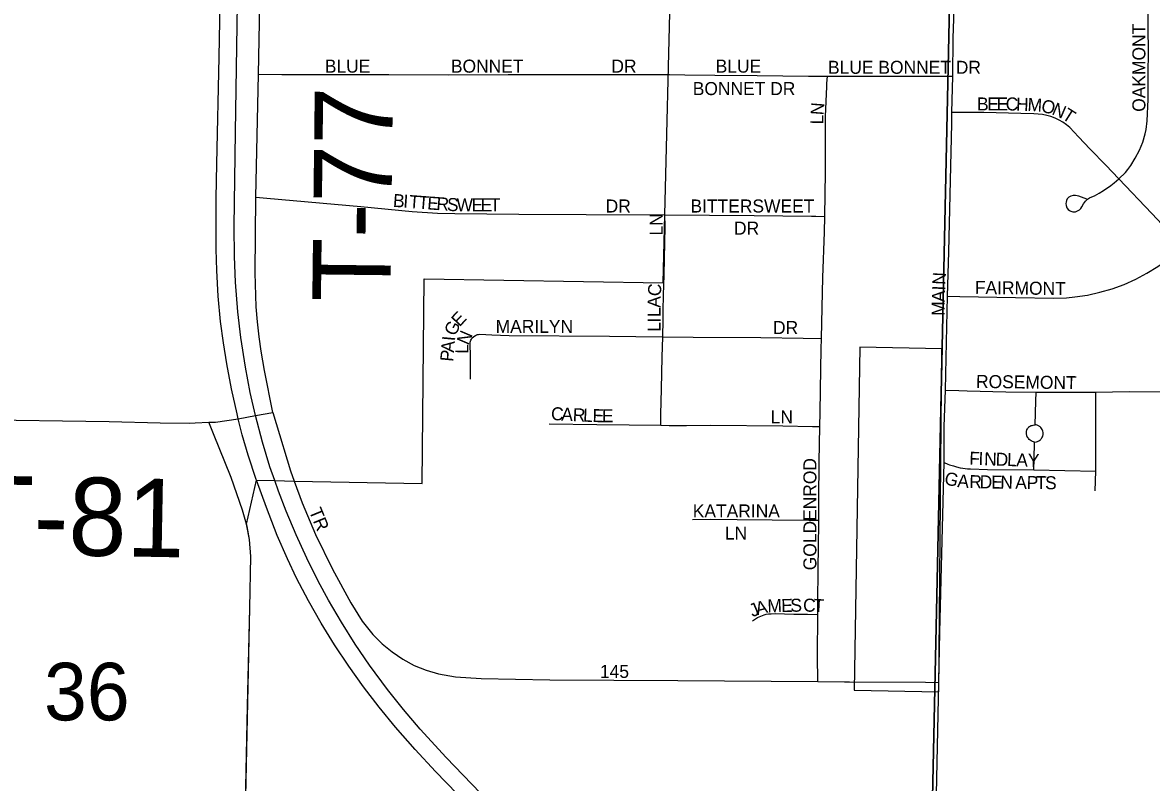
# Model space of a CAD drawing. Extents: x 1587405 to 1714697, y 1028970 to 1155083.
# Drawn here: x 1647315 to 1651648, y 1094719 to 1097636 of the extents above; entities that cross this region are included whole.
import ezdxf

# ---------------------------------------------------------------- set-up
doc = ezdxf.new("R2010")
doc.units = 0
for name, color, linetype in [('GM_X_City_Street', 7, 'Continuous'), ('GM_X_City_Street_Text', 7, 'Continuous'), ('GM_X_Corporation', 7, 'Continuous'), ('GM_X_Section', 7, 'Continuous'), ('GM_X_Section_Text', 7, 'Continuous'), ('GM_X_Township_Road', 7, 'Continuous'), ('GM_X_Township_Road_Text', 7, 'Continuous'), ('GM_X_Township_Subdivision', 7, 'Continuous'), ('GM_X_Township_Subdivision_Text', 7, 'Continuous'), ('GM_X_US_Route', 7, 'Continuous')]:
    doc.layers.add(name, color=color, linetype=linetype)

msp = doc.modelspace()

# ---------------------------------------------------------------- linework, layer by layer
at = {"layer": 'GM_X_City_Street'}
for points in [[(1650885.8, 1097429.9), (1650887.7, 1097576.5), (1650890.6, 1097688)], [(1651523.4, 1097036), (1651548.5, 1097060.6), (1651558.2, 1097072.2), (1651569.1, 1097087.2), (1651586.4, 1097116.2), (1651601.9, 1097145.8), (1651614.6, 1097176.7), (1651624.4, 1097208.8), (1651627.9, 1097225.3), (1651632, 1097258.6), (1651635.6, 1097341.1), (1651635.8, 1097374.3), (1651635.2, 1097407.5), (1651636.4, 1097556.2), (1651635.8, 1097585.7), (1651635.5, 1097635.4), (1651635.3, 1097685.8)], [(1649797.9, 1097436.5), (1649856.5, 1097435.3), (1649971.9, 1097434.7), (1650134.8, 1097433.1), (1650332.4, 1097430.7), (1650405.1, 1097430.5)], [(1650394, 1096891.5), (1650397, 1097061.4), (1650396.8, 1097275.7), (1650401.9, 1097391.1), (1650402.8, 1097402.6), (1650405.1, 1097430.5)], [(1650405.1, 1097430.5), (1650497.2, 1097430.2), (1650858.6, 1097429.9), (1650885.8, 1097429.9)], [(1650882.5, 1097290.6), (1650885.8, 1097429.9)], [(1650865.5, 1096586), (1650869.9, 1096756.5), (1650881.5, 1097248.5), (1650882.5, 1097290.6)], [(1651523.4, 1097036), (1651472.8, 1097088.4), (1651413, 1097150.2), (1651368.3, 1097198.2), (1651335.1, 1097233), (1651322.3, 1097244), (1651308.4, 1097253.7), (1651293.8, 1097262.2), (1651278.5, 1097269.3), (1651262.7, 1097275.2), (1651246.5, 1097279.8), (1651230, 1097283.1), (1651196.7, 1097286.3), (1651147.2, 1097287.6), (1651004.3, 1097290.7), (1650918.8, 1097290.6), (1650882.5, 1097290.6)], [(1651400.5, 1096958.2), (1651369.2, 1096969.7), (1651362.9, 1096971.3), (1651356.2, 1096972.8), (1651347.5, 1096972.3), (1651339, 1096970), (1651331.6, 1096965.9), (1651325.3, 1096959.1), (1651322.5, 1096953.8), (1651320.5, 1096947.1), (1651320.1, 1096941.4), (1651320.9, 1096933.4), (1651324, 1096925.3), (1651329.2, 1096918.4), (1651334.2, 1096914.5), (1651339.2, 1096911.7), (1651346.8, 1096909.5), (1651352.1, 1096909.5), (1651357, 1096910.2), (1651364.8, 1096913.3), (1651371.9, 1096917.3), (1651376.7, 1096922.1), (1651381.4, 1096929.5), (1651387.3, 1096939.9), (1651391.4, 1096945.6), (1651395.5, 1096950.4), (1651402.7, 1096957.8), (1651406.6, 1096961.1), (1651410.1, 1096963.3), (1651420, 1096967.5), (1651429.2, 1096971.7), (1651448.1, 1096981.9), (1651464.5, 1096991.5), (1651492.1, 1097010.5), (1651505, 1097021.3), (1651523.4, 1097036)], [(1651769, 1096776.9), (1651649.2, 1096903.2), (1651523.4, 1097036)], [(1649776.6, 1096628.6), (1649777.8, 1096668.4), (1649781.5, 1096853.5), (1649780.3, 1096898.1)], [(1649780.3, 1096898.1), (1650123.4, 1096895.7), (1650343.3, 1096893.5), (1650359.7, 1096892.9), (1650394, 1096891.5)], [(1650381.9, 1096423.3), (1650384.8, 1096542.5), (1650387.1, 1096657.5), (1650393, 1096832), (1650394, 1096891.5)], [(1650865.5, 1096586), (1650913.2, 1096585), (1651126.1, 1096580.3), (1651273.5, 1096578.9), (1651322.4, 1096580.2), (1651354.7, 1096582.8), (1651402.8, 1096590.4), (1651450.5, 1096601.3), (1651497.5, 1096614.6), (1651543.4, 1096631), (1651587.9, 1096651), (1651630.9, 1096674.1), (1651672.4, 1096699.9), (1651712.2, 1096728.3), (1651750, 1096759.1), (1651769, 1096776.9)], [(1649772.7, 1096430.2), (1649772.8, 1096446.3), (1649773.3, 1096478.9), (1649774.3, 1096531.3), (1649775.1, 1096590.2), (1649776.6, 1096628.6)], [(1650861.4, 1096409.8), (1650864, 1096526.9), (1650865.5, 1096586)], [(1649034.5, 1096266.9), (1649034, 1096295.4), (1649033.8, 1096348.7), (1649033.7, 1096409), (1649034.4, 1096413.5), (1649035.6, 1096416.7), (1649037.6, 1096420.6), (1649041.3, 1096425.5), (1649045.5, 1096429.7)], [(1649045.5, 1096429.7), (1649050.4, 1096433.4), (1649054, 1096435.5), (1649057, 1096437), (1649060.7, 1096438.3), (1649064.9, 1096439.2), (1649070.8, 1096439.7), (1649116.4, 1096437.4), (1649183.4, 1096435.6), (1649567.5, 1096432.6), (1649669.3, 1096431.4), (1649772.7, 1096430.2)], [(1649765.1, 1096090.7), (1649765.5, 1096131.6), (1649767.6, 1096230.6), (1649770.4, 1096351.4), (1649772.7, 1096430.2)], [(1649772.7, 1096430.2), (1649888.5, 1096428.8), (1650148.9, 1096427.2), (1650311.6, 1096424.8), (1650381.9, 1096423.3)], [(1650375.5, 1096085.3), (1650376.4, 1096140.2), (1650379, 1096307.6), (1650380.8, 1096382.5), (1650381.9, 1096423.3)], [(1650857.3, 1096224.8), (1650861.4, 1096409.8)], [(1650853.2, 1096086.2), (1650857.3, 1096224.8)], [(1650857.3, 1096224.8), (1650908.8, 1096223.4), (1650941.5, 1096222.5), (1651088.8, 1096218.4), (1651206.1, 1096218.1)], [(1651202.3, 1096092.3), (1651205, 1096183.3), (1651206.1, 1096218.1)], [(1651206.1, 1096218.1), (1651285.1, 1096217.8), (1651435, 1096217.8)], [(1651434.3, 1095914.1), (1651435.4, 1096152.3), (1651435, 1096217.8)], [(1651435, 1096217.8), (1651563, 1096220.1), (1651969, 1096215.9)], [(1649336.1, 1096096.5), (1649518.9, 1096093.9), (1649643.5, 1096092.1), (1649765.1, 1096090.7)], [(1649765.1, 1096090.7), (1649797.6, 1096090.1), (1649863.2, 1096089.5), (1649955, 1096090.2), (1650233.8, 1096088.2), (1650347.4, 1096085.8), (1650375.5, 1096085.3)], [(1650371.6, 1095726), (1650372, 1095805.5), (1650373.3, 1095949.9), (1650375.5, 1096085.3)], [(1650852.6, 1095947.4), (1650853.2, 1096086.2)], [(1651199.4, 1096026), (1651192.3, 1096028.1), (1651186, 1096031), (1651182.4, 1096033.5), (1651179.3, 1096036.2), (1651176.6, 1096039.4), (1651174.7, 1096041.7), (1651173, 1096044.1), (1651171.4, 1096046.8), (1651170.5, 1096049.1), (1651169.5, 1096051.9), (1651168.8, 1096055), (1651168.3, 1096058.1), (1651168.1, 1096061.5), (1651168.3, 1096064.3), (1651168.7, 1096067.1), (1651170.5, 1096073), (1651172, 1096076.5), (1651174.2, 1096079.7), (1651176.1, 1096082), (1651178.2, 1096084.1), (1651180.6, 1096085.9), (1651183.9, 1096087.7), (1651186.7, 1096089), (1651190.2, 1096090.1), (1651194.8, 1096091), (1651202.3, 1096092.3)], [(1651199.4, 1096026), (1651206.5, 1096026.9), (1651210.6, 1096028.1), (1651213.7, 1096029.4), (1651216.3, 1096030.7), (1651219.5, 1096032.7), (1651221.9, 1096034.8), (1651223.7, 1096036.9), (1651225.7, 1096039.3), (1651227.9, 1096042.4), (1651229.5, 1096045.5), (1651230.8, 1096048.4), (1651231.7, 1096051.4), (1651232.1, 1096054.1), (1651232.5, 1096059.2), (1651232.1, 1096063.1), (1651231.2, 1096067.2), (1651229.7, 1096071), (1651228.3, 1096074.3), (1651225.8, 1096078.1), (1651223.3, 1096081.4), (1651221, 1096083.8), (1651218.9, 1096085.7), (1651216.8, 1096087.2), (1651214.5, 1096088.5), (1651212.1, 1096089.7), (1651209.4, 1096090.6), (1651206, 1096091.6), (1651202.3, 1096092.3)], [(1651196.7, 1095918.9), (1651197.9, 1095960.5), (1651199.4, 1096026)], [(1650832, 1095103.5), (1650836.3, 1095296.8), (1650852.6, 1095947.4)], [(1650852.6, 1095947.4), (1650866.8, 1095941.5), (1650873.6, 1095938.7), (1650888.3, 1095934.2), (1650900, 1095930.7), (1650914.3, 1095927.4), (1650924.9, 1095925.5), (1650942.7, 1095923.8), (1650953.9, 1095923.2), (1651019.5, 1095920.7), (1651196.7, 1095918.9)], [(1651196.7, 1095918.9), (1651434.3, 1095914.1)], [(1651432.5, 1095838.9), (1651434.3, 1095914.1)], [(1648357.4, 1095876.4), (1648387.9, 1095792.1), (1648439.6, 1095671.2), (1648504.2, 1095538.2), (1648574.9, 1095408.4), (1648619, 1095338.7), (1648659.9, 1095286.8), (1648695, 1095251.6), (1648733.3, 1095220.1), (1648774.6, 1095192.3), (1648818.3, 1095168.7), (1648864.3, 1095149.9), (1648912.1, 1095136.3), (1648977.3, 1095125.4), (1649075.8, 1095118.5), (1649338.4, 1095113.4), (1649830.4, 1095111.3), (1650367.1, 1095106.6)], [(1649886.7, 1095729.3), (1649955.9, 1095729.4), (1650057.6, 1095729.1), (1650192.1, 1095727.9), (1650333.2, 1095726.4), (1650371.6, 1095726)], [(1650367.2, 1095364.1), (1650367.5, 1095401.9), (1650369.5, 1095546.3), (1650370.6, 1095618.5), (1650371.6, 1095723.5), (1650371.6, 1095726)], [(1650117.2, 1095340.3), (1650136.3, 1095352.2), (1650149, 1095358.1), (1650161.3, 1095362.5), (1650169.6, 1095364.7), (1650178.8, 1095366.4), (1650188.6, 1095367.2), (1650203.5, 1095367.7), (1650276.1, 1095365.7), (1650328.6, 1095364.8), (1650367.2, 1095364.1)], [(1650367.1, 1095106.6), (1650365.9, 1095205), (1650367.2, 1095364.1)], [(1650367.1, 1095106.6), (1650469.9, 1095106), (1650489.8, 1095105.8)], [(1650799.6, 1093622.9), (1650804.2, 1093857.2), (1650806.7, 1093968.4), (1650814.6, 1094247.2), (1650814.1, 1094296.5), (1650823, 1094673.5), (1650828, 1094919.6), (1650832, 1095103.5)]]:
    msp.add_lwpolyline(points, dxfattribs=at)
at = {"layer": 'GM_X_Corporation'}
msp.add_lwpolyline([(1648138.8, 1093097.3), (1648187.1, 1095389), (1648190.6, 1095586.4), (1648186.1, 1095652.4), (1648174.5, 1095711.3), (1648212.8, 1095880), (1648282.8, 1095878.2), (1648357.4, 1095876.4), (1648848.2, 1095866.6), (1648856.9, 1096652.9), (1649773.5, 1096636.9), (1649780.3, 1096898.1), (1649801.5, 1097777.7)], dxfattribs=at)
msp.add_lwpolyline([(1650529.5, 1096390.2), (1650506.5, 1095073.1), (1650832.5, 1095067.4), (1650843.4, 1096383.5)], close=True, dxfattribs=at)
at = {"layer": 'GM_X_Section'}
for points in [[(1645545.8, 1097805.3), (1650873.6, 1097703.2), (1650760.9, 1092453), (1645465, 1092544.3)], [(1650873.6, 1097703.2), (1656123.9, 1097642.2), (1656039.3, 1092397.9), (1655871.3, 1092400.1), (1650760.9, 1092453)]]:
    msp.add_lwpolyline(points, close=True, dxfattribs=at)
at = {"layer": 'GM_X_Township_Road'}
for points in [[(1648220, 1097437.7), (1648226.8, 1097771.2)], [(1648210.5, 1096966.1), (1648220, 1097437.7)], [(1648275.4, 1096139.9), (1648243.9, 1096300.1), (1648231.1, 1096375.2), (1648223.3, 1096430), (1648216.9, 1096487.1), (1648212, 1096544.6), (1648207.3, 1096676.1), (1648210.5, 1096966.1)], [(1647110.1, 1096112.9), (1647647.8, 1096105.2), (1647843.1, 1096099.7), (1647957.3, 1096098.3), (1647977.5, 1096099.3)], [(1648030.3, 1096101.8), (1648055.3, 1096102.9), (1648143.1, 1096115.6)], [(1648143.1, 1096115.6), (1648208.8, 1096128.3)], [(1648208.8, 1096128.3), (1648275.4, 1096139.9)], [(1648275.4, 1096139.9), (1648287.9, 1096097.4), (1648343.1, 1095915.7), (1648357.4, 1095876.4)], [(1647977.5, 1096099.3), (1648030.3, 1096101.8)], [(1648138.8, 1093097.3), (1648143.9, 1093353.9), (1648162.5, 1094207.7), (1648166.9, 1094454.1), (1648178.3, 1095012.2), (1648187.1, 1095389), (1648190.6, 1095586.4), (1648186.1, 1095652.4), (1648177.2, 1095701.4), (1648174.5, 1095711.3), (1648159.6, 1095765), (1648116.2, 1095889.3), (1648048.4, 1096057), (1648030.3, 1096101.8)], [(1650489.8, 1095105.8), (1650781.3, 1095103.8), (1650832, 1095103.5)]]:
    msp.add_lwpolyline(points, dxfattribs=at)
at = {"layer": 'GM_X_Township_Subdivision'}
for points in [[(1648220, 1097437.7), (1648310.2, 1097436.7), (1648432.6, 1097437), (1648720.8, 1097437.2), (1648949.6, 1097435.8), (1649178.5, 1097436.9), (1649603.4, 1097436.4), (1649797.9, 1097436.5)], [(1648210.5, 1096966.1), (1648253, 1096962.3), (1648613.3, 1096929.8), (1648809.8, 1096911.2), (1648908.1, 1096905.1), (1648973.7, 1096903.6), (1649220.5, 1096900.2), (1649478.1, 1096899.2), (1649780.3, 1096898.1)]]:
    msp.add_lwpolyline(points, dxfattribs=at)
at = {"layer": 'GM_X_US_Route'}
for points in [[(1648282.8, 1095878.2), (1648264.6, 1095930.6), (1648235.8, 1096025), (1648208.8, 1096128.3), (1648189, 1096216.7), (1648170.8, 1096313.7), (1648153.1, 1096427.5), (1648141.5, 1096525.4), (1648132.3, 1096640.2), (1648127.9, 1096738.8), (1648126.5, 1096853.9), (1648131.8, 1097215.2), (1648140.3, 1097707.7), (1648150.3, 1098233), (1648157.9, 1098676.3), (1648165.1, 1099070.3), (1648170.9, 1099365.8), (1648182.1, 1099891.1), (1648186.6, 1100203), (1648190.4, 1100400.1), (1648190.9, 1100425.2)], [(1649318.9, 1094329.7), (1648899.5, 1094761.5), (1648821.3, 1094845.4), (1648745.9, 1094931.8), (1648683.7, 1095007.8), (1648623.9, 1095085.8), (1648566.9, 1095165.9), (1648512.6, 1095247.7), (1648461, 1095331.3), (1648412.3, 1095416.7), (1648366.7, 1095503.6), (1648331.4, 1095577.5), (1648292.5, 1095667.7), (1648250.8, 1095774.5), (1648212.7, 1095880), (1648211.9, 1095882.4), (1648181.2, 1095975.8), (1648158.4, 1096054.3), (1648143.1, 1096115.6), (1648138.5, 1096133.7), (1648117.4, 1096229.7), (1648098.7, 1096326.3), (1648085.6, 1096407), (1648075.3, 1096488.2), (1648066.3, 1096586.1), (1648060.3, 1096684.1), (1648058, 1096766), (1648058.2, 1096962.7), (1648060.6, 1097093.8), (1648070.1, 1097503.8), (1648074.4, 1097782.7)], [(1649252.7, 1094492.5), (1649203.2, 1094543.2), (1648941.5, 1094815.6), (1648841.2, 1094924.3), (1648776.6, 1094998.8), (1648715.2, 1095076.2), (1648647.1, 1095169), (1648591.6, 1095250.6), (1648538.7, 1095334), (1648488.9, 1095419.2), (1648449.7, 1095491.4), (1648405.8, 1095579.9), (1648365, 1095669.7), (1648326.6, 1095760.6), (1648296.9, 1095837.3), (1648282.8, 1095878.2)]]:
    msp.add_lwpolyline(points, dxfattribs=at)

# ---------------------------------------------------------------- texts
at = {"layer": 'GM_X_City_Street_Text'}
for s, rotation, p in [('OAKMONT', 90, (1651625, 1097293.7)), ('BLUE', 0, (1649975.6, 1097443.9)), ('BLUE BONNET DR', 0, (1650406.8, 1097439.5)), ('BONNET DR', 0, (1649887.6, 1097357.9)), ('N', 85.7773, (1650389.3, 1097279.5)), ('B', 359.9757, (1650978.8, 1097298.7)), ('E', 359.9707, (1651018.4, 1097298.7)), ('E', 359.9707, (1651053.6, 1097298.7)), ('C', 359.9703, (1651088.8, 1097298.7)), ('H', 358.12, (1651127.9, 1097298.6)), ('M', 356.5373, (1651171.5, 1097297.2)), ('O', 347.0398, (1651222.1, 1097294.3)), ('N', 336.7211, (1651262.7, 1097285.2)), ('T', 327.621, (1651301.3, 1097268.8)), ('L', 88.8526, (1650388.6, 1097245)), ('BITTERSWEET', 0, (1649878.8, 1096907.1)), ('LN', 90, (1649772.6, 1096818.5)), ('DR', 0, (1650046, 1096822)), ('C', 85.795, (1649764.3, 1096584.4)), ('N', 87.1572, (1650857.1, 1096628.6)), ('FAIRMONT', 359.2148, (1650970.1, 1096594.7)), ('A', 88.6231, (1650855, 1096563)), ('I', 87.2446, (1650856.1, 1096606.7)), ('A', 89.4098, (1649763.9, 1096541.2)), ('M', 89.9271, (1650855, 1096510.5)), ('E', 47.1068, (1648992.2, 1096465.9)), ('L', 89.9457, (1649763.8, 1096506.1)), ('G', 64.2463, (1648975.3, 1096429.6)), ('MARILYN', 0, (1649130.8, 1096444.9)), ('I', 89.9126, (1649763.8, 1096484.1)), ('L', 89.9453, (1649763.8, 1096448.9)), ('DR', 0, (1650195.6, 1096440.5)), ('I', 84.7796, (1648974.6, 1096412.2)), ('N', 66.7899, (1649025.3, 1096395.3)), ('P', 84.7734, (1648967.3, 1096333.3)), ('A', 84.7462, (1648970.5, 1096368.3)), ('L', 89.5355, (1649026.1, 1096365.2)), ('ROSEMONT', 359.2456, (1650974.6, 1096233.9)), ('C', 357.157, (1649342.5, 1096110.7)), ('A', 357.1556, (1649382, 1096108.7)), ('R', 357.1645, (1649425.9, 1096106.5)), ('L', 357.1581, (1649465.5, 1096104.6)), ('E', 358.663, (1649502.1, 1096102.8)), ('E', 359.9073, (1649538.5, 1096102)), ('LN', 0, (1650186.8, 1096097.5)), ('F', 358.0326, (1650948.3, 1095939.1)), ('I', 357.9889, (1650983.5, 1095937.9)), ('N', 358.045, (1651005.5, 1095937.1)), ('D', 358.0326, (1651049.5, 1095935.6)), ('L', 358.0053, (1651093.5, 1095934.1)), ('A', 358.0337, (1651128.7, 1095932.9)), ('GOLDENROD', 90, (1650362.2, 1095533.7)), ('Y', 358.7429, (1651173.3, 1095931.3)), ('G', 345.5768, (1650849.8, 1095865.6)), ('A', 355.4999, (1650901.8, 1095853.1)), ('R', 358.5212, (1650948.5, 1095849.4)), ('D', 359.0694, (1650988.6, 1095848.4)), ('E', 359.2546, (1651032.8, 1095847.7)), ('N', 359.2495, (1651068, 1095847.2)), ('A', 359.2495, (1651125.2, 1095846.5)), ('P', 359.2546, (1651169.2, 1095845.9)), ('T', 359.2546, (1651204.4, 1095845.5)), ('S', 359.2546, (1651239.6, 1095845)), ('TR', 292.3821, (1648413.3, 1095761.6)), ('KATARINA', 0, (1649887.6, 1095736.5)), ('LN', 0, (1650010.8, 1095651.6)), ('M', 1.9674, (1650174.9, 1095371.5)), ('E', 1.4212, (1650227.6, 1095373.3)), ('S', 1.4509, (1650262.8, 1095374.1)), ('C', 358.8101, (1650310.6, 1095375.3)), ('T', 356.7747, (1650349.7, 1095374.5)), ('J', 23.0436, (1650116.8, 1095353)), ('A', 14.2907, (1650135.1, 1095361)), ('145', 0, (1649531.2, 1095120.6))]:
    msp.add_text(s, height=50, rotation=rotation, dxfattribs=at).set_placement(p)
at = {"layer": 'GM_X_Section_Text'}
msp.add_text('36', height=221, rotation=0, dxfattribs=at).set_placement((1647397.2, 1094957.6))
at = {"layer": 'GM_X_Township_Road_Text'}
for s, rotation, p in [('T-77', 89.3265, (1648726.9, 1096562.4)), ('T-81', 358.9397, (1647110.3, 1095598.3))]:
    msp.add_text(s, height=300, rotation=rotation, dxfattribs=at).set_placement(p)
at = {"layer": 'GM_X_Township_Subdivision_Text'}
for s, rotation, p in [('BLUE', 0, (1648475.2, 1097443.9)), ('BONNET', 0, (1648959.2, 1097443.9)), ('DR', 0, (1649575.2, 1097443.9)), ('B', 355.795, (1648735.5, 1096929.1)), ('I', 355.7991, (1648775, 1096926.2)), ('T', 355.7878, (1648796.9, 1096924.6)), ('T', 355.7843, (1648832, 1096922)), ('E', 355.7843, (1648867.1, 1096919.4)), ('R', 355.7949, (1648902.2, 1096916.8)), ('S', 356.9242, (1648942.8, 1096913.8)), ('W', 359.6583, (1648980.5, 1096911.9)), ('E', 359.9956, (1649038.1, 1096911.5)), ('E', 359.9956, (1649073.3, 1096911.5)), ('T', 359.9956, (1649108.5, 1096911.5)), ('DR', 0, (1649553.2, 1096907.1))]:
    msp.add_text(s, height=50, rotation=rotation, dxfattribs=at).set_placement(p)

doc.saveas('drawing.dxf')
